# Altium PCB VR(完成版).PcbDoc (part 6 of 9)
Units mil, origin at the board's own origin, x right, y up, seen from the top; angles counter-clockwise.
Board outline 2839.68 x 2020.7 mil, 6 copper layers (TOP, GND02, SIN03, SIN04, PWR05, BOTTOM); 494 components, 404 nets, 7124 pads, 1123 vias.
Unrouted connection lines stored in the file: 10.
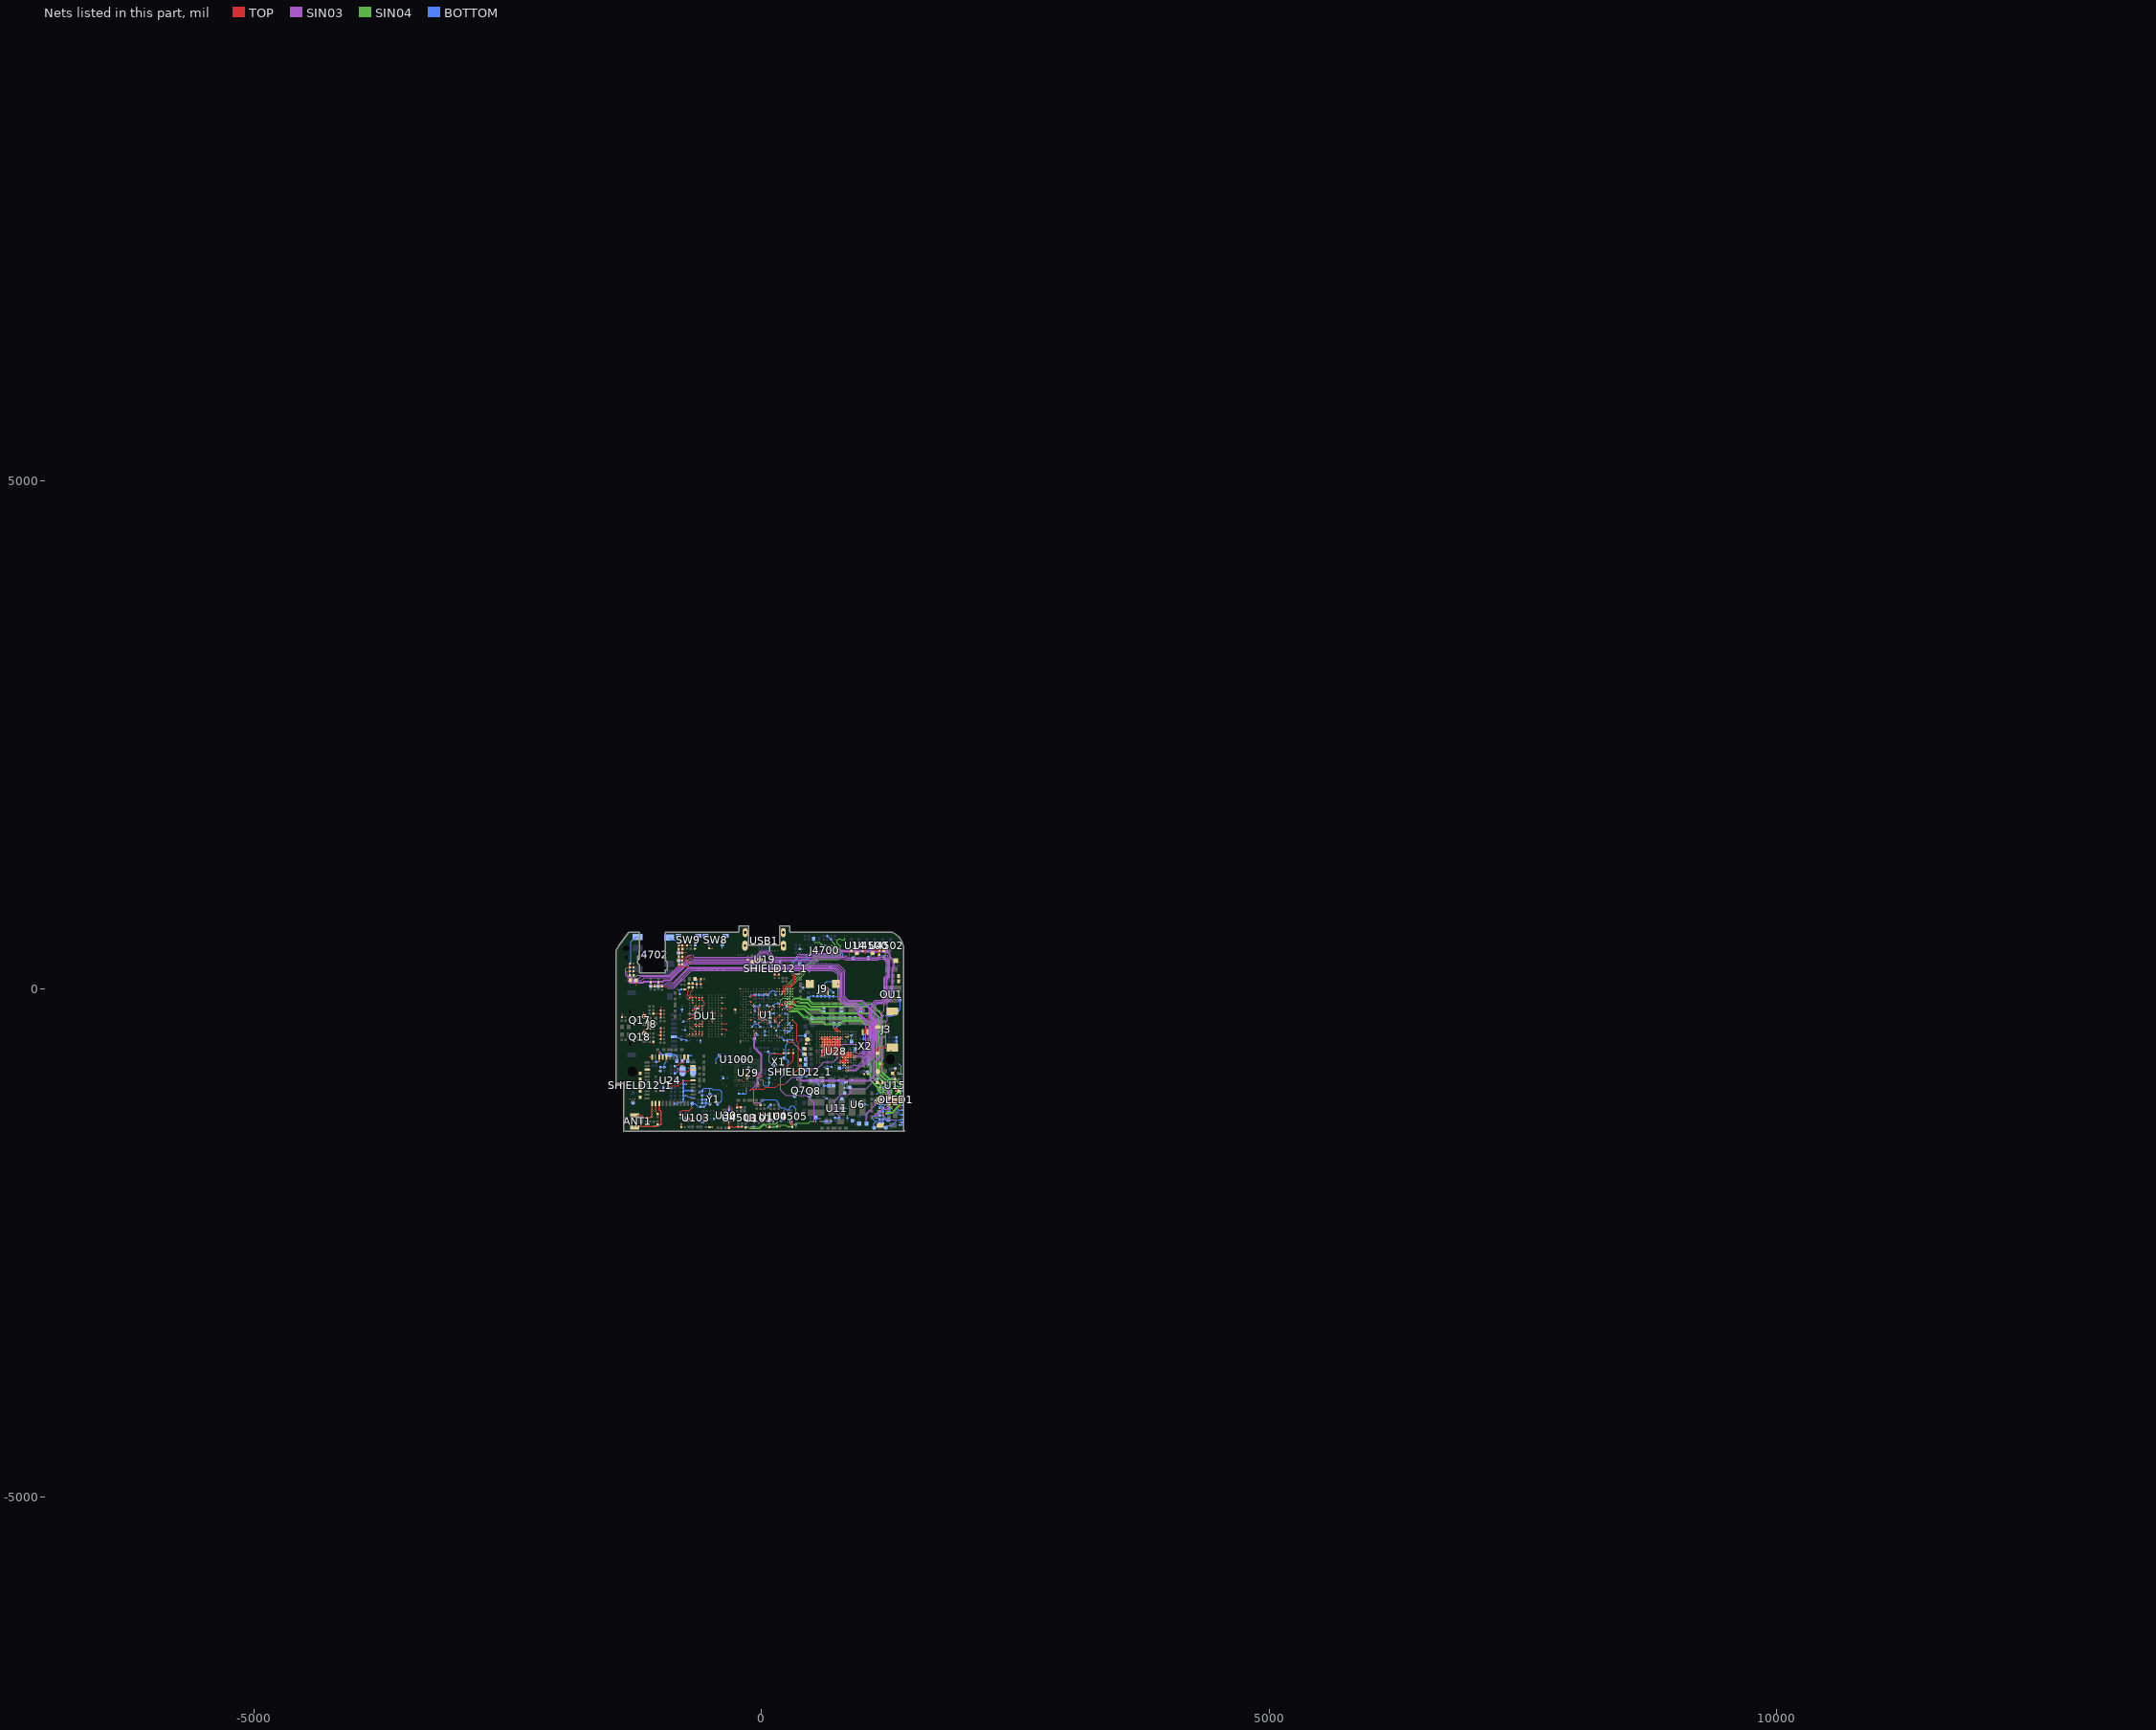
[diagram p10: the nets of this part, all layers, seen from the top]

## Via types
v1: diameter 14, hole 8, TOP to BOTTOM, tented both sides, 707 vias
v2: diameter 16, hole 10, TOP to BOTTOM, tented both sides, 275 vias
v3: diameter 16, hole 8, TOP to BOTTOM, tented both sides, 134 vias
v4: diameter 8, hole 8, TOP to BOTTOM, tented both sides, 3 vias
v5: diameter 10, hole 10, TOP to BOTTOM, tented both sides, 2 vias
v6: diameter 14, hole 8, TOP to BOTTOM, tented top, 1 vias
v7: diameter 14, hole 10, TOP to BOTTOM, tented both sides, 1 vias

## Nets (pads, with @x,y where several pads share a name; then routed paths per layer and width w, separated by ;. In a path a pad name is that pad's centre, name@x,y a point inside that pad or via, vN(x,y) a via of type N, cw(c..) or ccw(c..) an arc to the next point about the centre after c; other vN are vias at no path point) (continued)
GND: ANT1.2 ANT1.3 C3.2 C4.2 C5.1 C6.1 C7.2 C8.2 C11.1 C12.1 C13.2 C14.1 C15.2 C16.1 C17.1 C18.1 C19.1 C20.1 C21.1 C22.1 C23.1 C24.1 C25.1 C26.1 C27.1 C28.1 C29.1 C30.1 C31.1 C33.1 C34.1 C35.1 C36.1 C37.1 C38.1 C39.1 C41.1 C42.1 C43.1 C44.1 C45.1 C46.1 C47.1 C48.2 C50.2 C53.1 C56.2 C57.2 C59.2 C61.2 C63.2 C64.2 C65.1 C66.2 C67.2 C68.2 C69.1 C70.1 C71.1 C72.2 C74.1 C75.2 C76.1 C77.2 C78.1 C79.1 C81.1 C82.2 C83.2 C88.1 C89.1 C90.1 C91.1 C92.1 C93.1 C94.1 C95.1 C96.1 C98.1 C99.1 C100.1 C101.1 C117.1 C119.1 C130.1 C131.1 C132.1 C133.1 C134.1 C135.1 C136.1 C176.1 C179.1 C180.1 C182.1 C183.1 C184.1 C185.1 C186.1 C187.1 C188.1 C189.1 C190.1 C191.1 C197.2 C199.2 C200.1 C201.1 C202.2 C203.1 C204.2 C205.2 C216.2 C217.2 C218.2 C222.2 C226.1 C227.1 C228.1 C229.1 C230.1 C232.1 C233.1 C234.1 C236.2 C238.1 C239.2 C240.2 C241.2 C242.2 C247.2 C249.2 C261.2 C263.1 C265.1 C266.1 C267.1 C268.1 C269.1 C270.1 C271.2 C272.2 C273.2 C275.2 C276.1 C277.2 C278.2 C279.2 C280.1 C281.2 C282.2 C289.2 C290.1 C291.1 C292.2 C312.1 C313.1 C314.1 C315.1 C316.1 C317.1 C326.1 C327.1 C329.2 C331.2 C332.2 C333.2 C341.2 C4500.2 C4504.2 C4505.2 C4506.2 C4509.2 C4510.1 C4700.1 C4701.1 C4702.2 C4703.2 C4704.1 C4705.1 C4717.2 C4718.1 C4719.1 D2.2 D3.2 D13.2 D14.2 D15.2 D16.2 D17.2 D18.2 D19.2 D20.2 D21.2 D26.2 D27.2 D28.2 D29.2 D30.2 D31.2 D36.2 D37.2 D38.2 DC1.1 DC2.1 DC3.1 DC4.1 DC5.1 DC6.1 DC7.1 DC9.1 DC10.1 DC11.1 DC12.1 DC13.1 DC14.1 DC15.1 DC16.1 DC17.1 DC20.1 DC21.1 DC22.1 DC23.1 DR2.1 DR4.1 DR5.2 DR7.1 DU1.B2 DU1.B5 DU1.B6 DU1.B12 DU1.C3 DU1.C5 DU1.C6 DU1.D3 DU1.D12 DU1.E4 DU1.E5 DU1.E6 DU1.F4 DU1.F5 DU1.F6 DU1.F12 DU1.G3 DU1.G4 DU1.G6 DU1.G9 DU1.H2 DU1.H10 DU1.J4 DU1.J12 DU1.K2 DU1.K10 DU1.L6 DU1.L9 DU1.M4 DU1.M5 DU1.M6 DU1.M12 DU1.N4 DU1.N5 DU1.N6 DU1.P3 DU1.P12 DU1.R4 DU1.R5 DU1.R6 DU1.T2 DU1.T3 DU1.T4 DU1.T5 DU1.T6 DU1.T12 ED1.2 ED2.2 ED25.2 ED26.2 ED27.2 ED28.2 ED29.2 ED30.2 ED32.2 ED33.2 ED34.2 J3.3 J3.5 J3.6 J8.6 J8.10 J9.7 J9.8 J4700.1 J4700.3 J4700.16 J4700.25 J4700.29 J4700.31 OLED1.1 OLED1.7 OLED1.11 OLED1.15 OLED1.19 OLED1.23 OLED1.27 OLED1.31 OLED1.36 OLED1.40 OLED1.41 OU1.2 Q7.2 Q8.2 Q17.2 Q18.2 R8.2 R9.2 R14.2 R19.2 R23.2 R75.2 R87.2 R91.1 R137.1 R139.1 R149.1 R150.1 R151.1 R152.1 R168.1 R187.1 R193.1 R194.1 R325.1 R326.1 R465.1 R466.1 R478.1 R480.2 R484.1 R491.2 R1003.2 R1008.2 R1009.2 R4500.2 R4708.1 R5119.2 SHIELD12_1.1@141,198.14 SHIELD12_1.1@-1191.27,-949 SHIELD12_1.2@-1191.27,-1008.06 SHIELD12_1.3@383.73,-700.89 SHIELD12_1.3@-1191.27,-1067.11 SHIELD12_1.4@-1191.27,-889.94 SHIELD12_1.5@-1191.27,-830.89 SW8.2 SW8.3 SW8.4 SW9.2 SW9.3 SW9.4 TP62.1 TP71.1 U1.A1 U1.A21 U1.AA1 U1.AA21 U1.C7 U1.C11 U1.F5 U1.G6 U1.G16 U1.G17 U1.H6 U1.H8 U1.H12 U1.H14 U1.H16 U1.J8 U1.J13 U1.J17 U1.K5 U1.K8 U1.K9 U1.K10 U1.K11 U1.K12 U1.L8 U1.L16 U1.M8 U1.N5 U1.N9 U1.N10 U1.N11 U1.N12 U1.N14 U1.N17 U1.P8 U1.P12 U1.P16 U1.T14 U1.T18 U1.U6 U6.2 U11.2 U14.2 U15.2 U19.2 U24.1 U24.3 U24.20 U24.31 U24.33 U24.36 U28.D4 U28.D5 U28.D6 U28.D7 U28.E4 U28.E5 U28.E7 U28.F3 U28.F4 U28.F5 U28.F6 U28.G3 U28.G4 U28.G5 U28.G6 U28.G7 U28.G8 U28.G9 U28.G10 U28.G11 U28.G12 U28.G13 U28.G14 U28.H3 U28.H4 U28.H5 U28.H6 U28.H7 U28.H8 U28.H9 U28.H10 U28.H11 U28.H12 U28.H13 U28.H14 U28.J7 U28.J8 U28.J9 U28.J10 U28.J11 U28.J12 U28.J13 U28.J14 U28.K7 U28.K8 U28.K9 U28.K10 U28.K11 U28.K12 U28.K13 U28.K14 U28.L7 U28.L8 U28.L9 U28.L10 U28.L11 U28.L12 U28.L13 U28.L14 U28.M7 U28.M8 U28.M9 U28.M10 U28.M11 U28.M12 U28.M13 U28.M14 U28.N7 U28.N8 U28.N9 U28.N10 U28.N11 U28.N12 U28.N13 U28.N14 U28.P4 U28.P5 U28.P7 U28.P8 U28.P9 U28.P10 U28.P11 U28.P12 U28.P13 U28.P14 U29.AA4 U29.AA6 U29.K4 U29.M7 U29.P5 U29.R10 U29.U8 U29.Y2 U29.Y5 U30.11 U30.18 U30.20 U100.4 U100.8 U100.9 U101.3 U101.8 U101.11 U103.7 U1000.2 U4500.2 U4502.2 U4503.B1 U4505.1 U4505.6 U4505.7 USB1.5 USB1.6 USB1.7 USB1.8 USB1.9 X1.2 X1.4 X2.3 X2.4 Y1.2 Y1.4 | length 40403.1
  TOP w3.8: DU1.H2@-706.86,-241.03 -693.66,-254.23 v1@-656.29,-254.23
  TOP w4: DU1.K2@-706.49,-292.61 -696.17,-292.61 -683.08,-279.53 -666.4,-279.53 ; -662.99,-276.11 -651.08,-264.21 ; v1@-471.92,-303.66 -460.88,-292.61 DU1.K10@-454.52,-292.61 ; v1(-406.01,-253.02) -392.01,-267.02 DU1.J12@-391.53,-267.02 ; DU1.P12@-391.53,-394.98 -363.13,-394.98 -350.48,-407.63 -341.61,-407.63 v1(-331.01,-397.02) ; DU1.F12@-391.53,-190.25 v1@-347.23,-190.25
  TOP w5: -666.4,-279.53 -662.99,-276.11 ; -87.87,-64 -63.99,-64
  TOP w6: U24.36@-1126.27,-794.39 v1(-1086.61,-794.39) ; v1(-1102.67,-673.33) U24.33@-1076.08,-673.33 ; C201.1@-812.1,242.14 -812.1,222.1 -808,218 -732,218 v1(-721,229) ; U29.K4@-219.98,-898 v1(-182,-898) ; C13.2@132.86,140.28 C29.1@173,140.28 ; C13.2@133.73,142.87 v6(133.73,233.14)
  TOP w8: DU1.M12@-391.53,-343.8 v1@-348.81,-343.8 ; v1@-347.23,-190.25 v1(-346.26,-189.27)
  TOP w10: C326.1@-1371.1,-277.86 v1(-1371.1,-246.03) ; v1(-1322.94,210.81) D28.2@-1292.72,210.81 D27.2@-1292.72,249.14 ; v1(-1234.15,40.85) C190.1@-1234.15,85.14 ; Q18.2@-1152.27,-436.86 v1(-1152.27,-408.86) v1(-1134.27,-390.86) D14.2@-1095.37,-390.86 v1(-1095.37,-370.86) -1095.37,-341.86 C176.1@-1094.39,-341.86 ; Q17.2@-1152.27,-270.86 v1(-1152.27,-235.86) ; v1(-1064.92,-553.86) R480.2@-1064.92,-521.86 ; R478.1@-1064.92,-244.86 -992.62,-244.86 D20.2@-990.1,-247.37 ; R150.1@-1051.61,27.52 v1(-1051.61,51.48) ; v1(-1018.27,-456.86) D16.2@-990.1,-456.86 ; v2(-1005.22,-712.78) U24.31@-1005.22,-673.33 -1005.22,-627.22 v1(-1004,-626) ; D21.2@-990.1,-494.01 D16.2@-990.1,-458.78 D16.2@-990.1,-456.86 ; D18.2@-990.1,-388.31 D17.2@-990.1,-423.54 D16.2@-990.1,-456.86 ; D19.2@-990.1,-282.61 D20.2@-990.1,-247.37 ; v1(-990.1,-183.03) D15.2@-990.1,-212.14 D20.2@-990.1,-247.37 ; R151.1@-978.27,27.52 -953.48,27.52 -941,40 v1(-941,66) ; v1(-825,-786) -800,-811 -720,-811 -703.39,-794.39 U24.20@-671.55,-794.39 ; C333.2@-796.2,-1240.1 -796.2,-1213.2 -778,-1195 -707,-1195 -681.15,-1169.15 v2(-681.15,-1159) ; DC9.1@-756.72,-4.86 v1(-732.14,-4.86) ; v1(-744.06,354.94) C200.1@-779.82,354.94 D26.2@-779.82,430.14 -731.44,430.14 C79.1@-730.27,428.97 ; v1(-724.82,-297.23) -724.61,-297.02 -710.9,-297.02 DU1.K2@-706.49,-292.61 ; v1(-724.58,-241.43) DU1.H2@-706.49,-241.43 ; v1(-720.13,-100.68) DU1.B2@-707.33,-87.89 ; v1@-719.28,-458.95 DU1.T2@-706.49,-446.16 ; DR2.1@-715.27,53.35 -710.34,48.43 DC10.1@-637.27,48.43 DC23.1@-596.27,48.43 ; v1(-693.69,-382.18) -680.9,-394.98 DU1.P3@-674.99,-394.98 ; v1(-688.63,-433.36) DU1.T3@-675.84,-446.15 ; v1(-688.63,-100.68) -675.84,-113.48 -679.42,-117.06 -679.42,-135.48 DU1.D3@-675.84,-139.07 ; v1@-687.78,-458.95 DU1.T3@-674.99,-446.16 ; v1@-659.74,-353.46 v1@-659.42,-353.46 ; v1(-657.13,-407.77) -644.34,-420.56 -644.34,-445.31 DU1.T4@-643.49,-446.16 v1@-656.29,-458.95 ; v1@-656.29,-254.23 DU1.J4@-643.49,-267.02 ; D2.2@-656.27,395.69 v1(-632.82,395.69) ; DC12.1@-652.15,98.14 v1(-623.14,98.14) ; DU1.F4@-643.49,-190.25 v1(-656.29,-177.46) DU1.E4@-643.49,-164.66 ; v1(-625.79,-77.09) -622.79,-77.09 DU1.B5@-612,-87.89 DU1.C5@-612,-113.48 ; v1@-624.79,-458.95 DU1.T5@-612,-446.16 DU1.R5@-612,-420.57 ; DU1.M5@-612,-343.8 -606.09,-343.8 v1(-593.3,-356.59) ; DU1.F5@-612,-190.25 v1(-624.79,-177.46) DU1.E5@-612,-164.66 ; v1@-596.27,72.27 DC23.1@-596.27,48.43 ; v1(-593.3,-203.05) DU1.G6@-580.5,-215.84 ; v1@-593.3,-458.95 DU1.T6@-580.5,-446.16 DU1.R6@-580.5,-420.57 ; v1@-593.3,-75.09 DU1.B6@-580.5,-87.89 -580.5,-88.31 -588.08,-95.89 -588.08,-105.9 DU1.C6@-580.5,-113.48 -580.5,-117.11 -558.86,-138.75 -558.86,-152.81 -568.58,-162.53 DU1.E6@-578.58,-162.53 ; DC11.1@-593.28,96 -596.27,93.01 DC23.1@-596.27,48.43 ; DU1.N6@-580.5,-369.39 v1(-593.3,-356.59) ; DU1.L6@-580.5,-318.2 DU1.M6@-580.5,-343.8 v1(-593.3,-356.59) ; DU1.F6@-580.5,-190.25 v1(-593.3,-177.46) DU1.E6@-580.5,-164.66 ; D38.2@-515.27,399.86 v1@-487.56,399.86 ; DU1.L9@-486.01,-318.2 v1(-473.22,-331) ; DU1.G9@-484.08,-216.14 -479.81,-216.14 DU1.H10@-454.52,-241.43 ; DU1.T12@-391.53,-446.16 v1@-378.58,-446.16 ; DU1.D12@-391.53,-139.07 v1@-373.43,-139.07 ; DU1.B12@-391.53,-87.89 -386.55,-82.91 -377.01,-82.91 v1@-375.74,-81.63 ; v1@-348.81,-343.8 -347.03,-342.02 v1(-344.01,-342.02) ; v2(-314.27,-1154.86) -286.21,-1182.92 U30.18@-286.21,-1209.49 ; v1(-221.98,0) U1.A1@-203.88,0 ; U29.K4@-221.22,-896.76 U29.K4@-219.98,-898 ; v1(-204.03,-530.91) U1.AA1@-204.03,-511.96 ; U29.M7@-181.85,-837.7 -145.7,-837.7 -135,-827 v1(-135,-807) -122.8,-794.8 U29.R10@-122.8,-778.65 ; U29.P5@-142.48,-877.07 -142.48,-891.52 v1(-135,-899) ; v1(-115.15,-294.29) U1.N5@-102.36,-307.09 ; v1(-115.15,-243.11) U1.K5@-102.36,-230.32 ; v1(-114.3,-115.17) U1.F5@-101.51,-127.96 ; v1(-113.46,-89.58) -87.87,-64 ; C184.1@-85.27,266.02 -63.15,288.14 U19.2@-16.45,288.14 ; U29.U8@-83.43,-818.02 v1(-64.02,-818.02) ; U1.U6@-76.77,-409.45 v1(-63.97,-422.24) ; U1.H6@-75.92,-179.14 v1(-88.72,-166.34) U1.G6@-75.92,-153.56 ; -63.99,-64 U1.C7@-51.18,-51.19 U1.C7@-51.18,-52.04 ; v1(-38.39,-345.48) U1.P8@-25.59,-332.68 ; v1(-38.39,-294.3) U1.M8@-25.59,-281.5 U1.N9@0,-307.09 v1(12.79,-319.89) U1.N10@25.59,-307.09 ; v1(-38.39,-268.7) U1.L8@-25.59,-255.91 -12.79,-243.11 ; v1(-38.39,-191.93) U1.H8@-25.59,-179.14 ; v1(-38.39,-191.93) U1.J8@-25.59,-204.73 ; v1(-24.37,-971.63) U29.Y2@-24.37,-936.13 ; U29.Y5@-24.37,-877.07 U29.AA6@-4.69,-857.39 v1(20.39,-857.39) ; U29.AA4@-4.69,-896.76 v1(20.76,-896.76) ; U1.K9@0,-230.32 v1(-12.8,-217.52) U1.J8@-25.59,-204.73 ; v1(38.39,-38.39) U1.C11@51.18,-51.19 ; U1.N11@51.18,-307.09 v1(63.98,-319.89) ; v1@63.98,-345.48 U1.P12@76.77,-332.68 v1(63.98,-319.89) ; U1.N12@76.77,-307.09 v1(63.98,-319.89) ; U1.H12@76.77,-179.14 v1(89.57,-166.34) ; v1(94,-640) 212.92,-640 C8.2@222,-630.92 C8.2@223.36,-632.28 ; U1.N14@127.95,-307.09 v1(166.33,-345.48) U1.P16@179.13,-332.68 U1.N17@204.72,-307.09 v1(217.52,-294.29) ; U1.T14@127.95,-383.86 v1(140.75,-396.65) ; U1.N14@127.95,-307.09 U1.L16@179.13,-255.91 v1(191.93,-268.7) ; U1.H14@127.95,-179.14 U1.K12@76.77,-230.32 v1(63.98,-217.52) U1.K11@51.18,-230.32 38.39,-217.52 U1.K10@25.59,-230.32 v1(12.79,-217.52) -12.79,-243.11 ; v1(172.86,-793) 225,-793 314,-704 C280.1@314,-632.28 313,-631.28 C277.2@268,-631.28 ; U1.H16@179.13,-179.14 U1.G17@204.72,-153.55 v1(191.92,-140.76) U1.G16@179.13,-153.55 ; U1.J17@204.72,-204.73 v1(217.52,-191.93) ; U1.T18@230.31,-383.86 v1(243.11,-396.65) ; U1.AA21@307.09,-511.82 v1(319.89,-499.01) ; U1.A21@307.09,0 v1(319.89,12.8) ; R14.2@438.06,-540.48 438.06,-513.8 C265.1@454,-497.86 ; 661.84,-638.62 U28.G11@674.63,-651.42 ; U28.H11@674.63,-625.83 v3(687.44,-638.63) ; U28.P5@828.18,-472.28 U28.P4@853.77,-472.28 ; v1@866.73,321.14 866.73,354.86 C204.2@886.73,374.86 ; v1(923.73,325.14) 923.73,334.02 C205.2@940.73,351.02 ; C4506.2@996.73,374.31 1013.69,374.31 1023.73,364.27 v1@1023.73,339.14 ; v1(1078.23,325.14) 1078.23,332.52 C4504.2@1096.73,351.02 1125.02,379.31 C4509.2@1161.73,379.31 ; C117.1@1143.73,-635.86 C117.1@1143.73,-635.33 ; 1143.73,-601.86 C117.1@1143.73,-635.33 ; C132.1@1146.38,-812.61 1173.73,-785.26 C119.1@1173.73,-737.86 1205.73,-737.86 v2@1205.73,-736.86 ; R4500.2@1161.73,337.52 C4509.2@1161.73,379.31 ; J3.3@1176.25,-374.25 1219.33,-374.25 v2(1247.73,-345.86) ; C4510.1@1204.61,378.14 1203.44,379.31 C4509.2@1162.73,379.31 C4509.2@1161.73,379.31 ; v2(1226.73,-1159.86) 1231.73,-1159.86 1258.56,-1133.02 C16.1@1258.56,-1129.83 ; J3.5@1290.42,-576.02 1157.98,-576.02 1143.73,-590.27 C117.1@1143.73,-635.33 ; U15.2@1316.73,-898.86 1316.73,-856.98 C216.2@1292.61,-832.86 1321.87,-803.6 C133.1@1321.87,-782.86 ; D3.2@1321.13,276.14 1325.13,272.14 v1(1362.73,272.14) ; v2(1354.16,-1179) 1379,-1154.16 C236.2@1379,-1105.28 ; v1@-659.42,-353.46 -659.08,-353.8 DU1.N4@-643.49,-369.39 -637.59,-369.39 -624.79,-356.59 ; v1@-659.42,-353.46 -655.44,-353.46 -645.78,-343.8 DU1.M4@-643.49,-343.8 -643.49,-346.59 -633.49,-356.59 -624.79,-356.59 ; -624.79,-356.59 DU1.N5@-612,-369.39 -606.09,-369.39 v1(-593.3,-356.59) ; U1.AA1@-204.03,-511.96 -203.88,-511.82 U1.AA1@-204.03,-511.96 ; U1.J8@-25.59,-204.73 v1(-38.39,-217.52) U1.K8@-25.59,-230.32 -12.79,-243.11
  TOP w11.81: ANT1.2@-1247.29,-1246.79 -1179.34,-1246.79 v2(-1161.27,-1264.86) -1082.27,-1264.86 v2(-1076.08,-1258.67) U24.1@-1076.08,-1128.05 ; v2(-1196.27,-1352.86) -1030.86,-1352.86 -1020,-1342 -995.41,-1342 v2(-987.27,-1333.86) -987.27,-1208.86 -1005.22,-1190.91 U24.3@-1005.22,-1128.05 ; C331.2@-787.1,-1360.86 v2(-787.1,-1332.03) ; U103.7@-732.85,-1283.65 v2(-676.27,-1283.65) ; C329.2@-512.44,-1360.86 -511.44,-1361.86 v2(-485.27,-1361.86) ; U30.11@-321.65,-1307.92 -321.65,-1323.48 -316.89,-1328.24 R168.1@-316.89,-1366.86 -308.72,-1358.69 C191.1@-228.27,-1358.69 C189.1@-192.27,-1358.69 ; U30.20@-321.65,-1189.8 -321.65,-1162.24 v2(-314.27,-1154.86) ; v2(-250.07,-1269.06) U4503.B1@-228.97,-1269.06 ; v1(-239.27,-1135.86) C186.1@-239.27,-1168.03 -237.72,-1166.48 R491.2@-202.55,-1166.48 ; v7(-100.27,-1304) -100.27,-1284.27 -88.86,-1272.86 U101.3@-74.58,-1272.86 ; U101.8@20.03,-1292.54 51.41,-1292.54 v2(55.73,-1296.86) 76.55,-1296.86 U100.4@90.02,-1283.39 ; U101.11@20.03,-1233.49 20.03,-1220.55 v2(27.23,-1213.36) ; U100.8@151.44,-1263.7 U100.9@151.44,-1244.02 170.57,-1244.02 190.26,-1224.33 U4505.1@221.69,-1224.33 v2(221.69,-1195.9) ; C179.1@154.73,-1356.69 v2(183.56,-1356.69) ; U4505.6@281.73,-1304.05 281.73,-1326.86 287.73,-1332.86 v2@301.41,-1332.86 ; U4505.7@301.41,-1304.05 v2@301.41,-1332.86 ; C4719.1@303.56,-1359.86 301.41,-1357.71 v2(301.41,-1333.86) v2@301.41,-1332.86 ; v3(585.07,-664.22) U28.G14@597.86,-651.42 ; v3(585.07,-638.63) U28.H14@597.86,-625.83 U28.K12@649.04,-574.65 v3(661.84,-561.85) ; v3(585.07,-561.85) U28.K14@597.86,-574.65 v3(610.66,-561.85) ; U28.J14@597.86,-600.24 U28.G12@649.04,-651.42 U28.J10@700.23,-600.24 U28.K9@725.82,-574.65 ; U28.L14@597.86,-549.05 v3(610.66,-536.26) ; v3(610.66,-664.22) U28.G13@623.45,-651.42 U28.K10@700.23,-574.65 ; v3(610.66,-638.63) U28.H13@623.45,-625.83 U28.J12@649.04,-600.24 v3(661.84,-587.44) ; v3(610.66,-587.44) U28.J13@623.45,-600.24 661.84,-638.62 U28.G11@674.63,-651.42 ; U28.M13@623.45,-523.46 636.25,-536.26 ; U28.P13@623.45,-472.28 610.66,-485.08 ; U28.P12@649.04,-472.28 v3(636.25,-485.07) ; U28.H11@674.63,-625.83 U28.K13@623.45,-574.65 ; U28.P11@674.63,-472.28 v3(661.84,-485.07) ; U28.N10@700.23,-497.87 U28.M9@725.82,-523.46 U28.L8@751.41,-549.05 ; U28.P10@700.23,-472.28 738.62,-510.66 ; U28.P9@725.82,-472.28 U28.L12@649.04,-549.05 U28.K13@623.45,-574.65 ; v3(764.21,-587.44) U28.J8@751.41,-600.24 U28.G10@700.23,-651.42 v3(687.44,-638.63) U28.H10@700.23,-625.83 U28.L7@777,-549.05 U28.M8@751.41,-523.46 ; 764.21,-536.26 U28.M7@777,-523.46 764.21,-510.67 ; U28.D7@777,-728.19 U28.H3@879.36,-625.83 v3(892.16,-638.63) U28.D6@802.59,-728.19 ; U28.E7@777,-702.6 U28.D6@802.59,-728.19 ; U28.G7@777,-651.42 U28.H6@802.59,-625.83 ; U28.J7@777,-600.24 U28.L9@725.82,-549.05 v3(713.03,-536.26) ; U28.P7@777,-472.28 v3(789.8,-485.07) U28.N7@777,-497.87 764.21,-510.67 ; 789.38,-613.45 U28.H7@777,-625.83 ; 789.79,-663.21 827.17,-625.83 U28.H5@828.18,-625.83 840.98,-638.62 U28.G4@853.77,-651.42 U28.F3@879.36,-677.01 892.16,-664.22 U28.G3@879.36,-651.42 866.57,-638.62 U28.H4@853.77,-625.83 ; v3(815.39,-740.98) U28.D6@802.59,-728.19 ; v3(815.39,-740.98) U28.D5@828.18,-728.19 ; U28.E5@828.18,-702.6 U28.D4@853.77,-728.19 ; 840.98,-715.4 U28.E4@853.77,-702.6 ; U28.H4@853.77,-625.83 U28.F6@802.59,-677.01 U28.K10@700.23,-574.65 ; U28.P4@853.77,-472.28 v3(866.56,-459.49) ; X2.3@1001.19,-426.06 1024,-426.06 ; C233.1@1012.66,-838.69 C232.1@1052.66,-838.69 ; v2(1044,-378.57) 1024,-398.57 1024,-426.06 ; X2.4@1048.44,-426.06 1024,-426.06 ; U28.N14@597.86,-497.87 610.66,-485.08 ; U28.N14@597.86,-497.87 v3(661.84,-561.85) ; U28.N14@597.86,-497.87 v3(585.07,-485.07) U28.P14@597.86,-472.28 610.66,-485.07 ; v3(610.66,-561.85) 661.84,-510.66 ; v3(610.66,-561.85) U28.K13@623.45,-574.65 ; v3(610.66,-536.26) v3(661.84,-485.07) ; v3(610.66,-536.26) U28.L13@623.45,-549.05 v3(661.84,-587.44) ; v3(610.66,-536.26) U28.M14@597.86,-523.46 v3(636.25,-485.07) ; 610.66,-485.07 U28.N13@623.45,-497.87 U28.M12@649.04,-523.46 U28.L11@674.63,-549.05 U28.K10@700.23,-574.65 ; v3(636.25,-485.07) 661.84,-510.66 ; v3(661.84,-587.44) U28.K11@674.63,-574.65 ; v3(661.84,-587.44) U28.J11@674.63,-600.24 U28.G9@725.82,-651.42 U28.J7@777,-600.24 ; v3(661.84,-561.85) U28.M10@700.23,-523.46 v3(713.03,-510.66) U28.P8@751.41,-472.28 v3(764.21,-485.07) U28.N8@751.41,-497.87 738.62,-510.67 ; v3(661.84,-561.85) U28.K11@674.63,-574.65 ; 661.84,-510.67 U28.N11@674.63,-497.87 ; 661.84,-510.66 U28.M11@674.63,-523.46 v3(713.03,-561.85) ; v3(661.84,-485.07) U28.N11@674.63,-497.87 ; U28.K11@674.63,-574.65 U28.G8@751.41,-651.42 v3(764.21,-638.63) U28.H7@777,-625.83 ; U28.K11@674.63,-574.65 U28.L10@700.23,-549.05 v3(713.03,-536.26) ; U28.N11@674.63,-497.87 v3(713.03,-536.26) ; U28.K10@700.23,-574.65 v3(713.03,-561.85) ; v3(713.03,-561.85) U28.M8@751.41,-523.46 ; v3(713.03,-561.85) U28.K9@725.82,-574.65 ; v3(713.03,-536.26) 738.62,-510.66 ; U28.K9@725.82,-574.65 U28.H7@777,-625.83 ; U28.K9@725.82,-574.65 U28.L8@751.41,-549.05 ; 738.62,-510.66 U28.M8@751.41,-523.46 ; U28.L8@751.41,-549.05 v3(789.8,-587.44) U28.J7@777,-600.24 ; U28.M8@751.41,-523.46 764.21,-510.67 ; U28.H7@777,-625.83 U28.F5@828.18,-677.01 v3(840.98,-689.81) U28.F4@853.77,-677.01 v3(840.98,-664.22) U28.G5@828.18,-651.42 U28.J7@777,-600.24
  TOP w12: DU1.G3@-675.84,-215.84 -666.9,-206.9 -653.28,-206.9 -644.34,-215.84 DU1.F4@-644.34,-190.25 ; v1(-274.01,-202.02) -271.29,-204.74 DC7.1@-254.01,-204.74
  SIN03 w6: -1339,194.75 -1339,132 -1276,69 -1166,69 -1159,76 -972,76 -956,92 -894,92 -714,272 -697,272 ; -1295,198 -1295,129 -1260,94 -1215,94 -1186,123 -899,123 -739,283 -739,305 -714,330 v1(-678,330) -661,313 -65,313 -4,374 71,374 132,313 516,313 544,341 767,341 792,366 1206.87,366 v1(1232.73,340.14) 1247,325.87 1247,309 1266,290 1266,122 1240,96 1240,-107 1201,-146 1145,-146 1127,-164 1127,-253 1153,-279 1153,-526 1138,-541 1138,-647 1039,-746 ; v1@-940,65 -868,65 -717,216 736,216 794,158 794,-85 842,-133 933,-133 1008,-208 1008,-233 1037,-262 v2(1037,-281) 1037,-284 1084,-331 1084,-487 1070,-501 1070,-601 1012.5,-658.5 ; v1(-921,8) -861,8 -687,182 710,182 754,138 754,-102 824,-172 902,-172 951,-221 951,-259 1029,-337 1029,-581 987,-623 966,-623 ; -697,278.44 -697,272 ; v1(-697,286) -697,272 ; 996,-731 1103,-624 1103,-524 1118,-509 1118,-313 1086,-281 1086,-147.02 1121.02,-112 1183,-112 1206,-89 1206,110.08 1232,136.08 1232,264.92 1200.92,296 1161,296 1152,287 831,287 817,301 581,301 552,272 -697,272
  SIN03 w10: -1339,194.75 v1(-1322.94,210.81)
  SIN04 w6: v1(191.92,-140.76) 191.92,-113.08 215.02,-89.98 268.02,-89.98 288,-70 288,18 559,289 761,289 778,306 778,415 745,448 745,480 758,493 780,493 792,481 817,481 821,485 v1(821,510) ; 196,-66 196,-54 241,-9 241,26 541,326 706.32,326 v1(729.92,349.6) 730,349.68 730,394 696,428 604,428 570.86,461.14 v1(523.73,461.14) ; v1(243.1,-63.98) 266,-41.09 266,23 550,307 731,307 754,330 754,404.53 v1(687.06,471.47)
  BOTTOM w5: v1(-63.97,-422.24) -63.97,-426.31 C3.2@-40.14,-450.14
  BOTTOM w6: v1(-1013.24,-807.24) R466.1@-993.27,-807.24 ; v1(-821,-5) DC4.1@-788.28,-5 -802.27,-18.99 DC21.1@-802.27,-53.57 ; D29.2@-779.82,239.14 -731.14,239.14 v1(-721,229) ; v6@133.73,237.14 158.87,212 165,212 184.73,231.73 C182.1@184.73,270.41 ; C4702.2@378.61,245.14 378.61,272.61 401.14,295.14 445.73,295.14 ; v1(468,356.14) 468,324.55 J4700.3@470.07,322.48
  BOTTOM w8: R1009.2@1163.35,-1168.24 C4717.2@1196.73,-1134.86
  BOTTOM w10: R194.1@-1034.89,-718.86 -1028.82,-712.78 v2(-1005.22,-712.78) ; R193.1@-965,-974.31 v1(-965,-949) ; J8.6@-859.74,-472.81 v1(-818.23,-472.81) -791.89,-499.14 DC17.1@-785.27,-499.14 -747.86,-499.14 DC1.1@-736.58,-510.42 ; C238.1@-854.82,-1130.86 -824.86,-1130.86 -809,-1115 -775,-1115 -767.44,-1107.44 C312.1@-767.44,-1089.86 ; R465.1@-853.27,-832.48 -845.48,-832.48 -825,-812 v1(-825,-786) ; v1(-785.41,-339) DC15.1@-766.27,-319.86 ; v1@-780.42,-233.9 DC20.1@-780.42,-204.19 ; v1(-779.86,-405.14) DC3.1@-751.27,-405.14 ; v2(-736.27,-1051.11) -726.52,-1060.86 -701.27,-1060.86 -695.27,-1066.86 -658.14,-1066.86 ; v1(-724.58,-241.43) -718.1,-247.91 -662.61,-247.91 v1@-656.29,-254.23 ; v2(-681.15,-1159) C234.1@-681.15,-1129.86 -652.14,-1129.86 -615.97,-1166.03 C241.2@-597.1,-1166.03 ; v1(-656.29,-177.46) -656.29,-200.75 -652.14,-204.9 ; DC6.1@-637,48.14 -637,84.28 v1(-623.14,98.14) ; -618.13,-1026.13 -598,-1006 C240.2@-583.28,-1006 -583.28,-997.28 -564,-978 -523,-978 ; v1(-598.91,-536.91) DC22.1@-598.91,-510.42 ; v1(-476.83,-1037.17) Y1.4@-505.99,-1037.17 -505.99,-995.01 -523,-978 ; v1@-447,-1099.86 -428.03,-1118.83 -408.01,-1118.83 -388,-1098.82 -388,-1016.01 -412,-992.01 -479.99,-992.01 -494,-978 -523,-978 ; v1(-447,-732) -447,-692 C341.2@-413,-658 ; v1(-383.92,400.79) SW8.2@-383.92,446.37 ; R326.1@-375.38,-878 v1(-375.38,-849.38) ; v1@-234,-674 -213,-695 U1000.2@-181.16,-695 ; C96.1@-220.6,-1032.69 C95.1@-181.64,-1032.69 -155.69,-1032.69 -145,-1022 v1(-145,-973) ; v1(-135,-899) -135,-874.28 C101.1@-128.72,-868 ; -129,-798 -129,-776.17 C99.1@-125.83,-773 ; v1@-129,237.14 R137.1@-42.65,237.14 -38.27,241.52 D36.2@-38.27,275.31 D31.2@-1.27,275.31 D30.2@34.73,275.31 ; v1(-113.46,-89.58) -113.46,-71.46 -100.72,-58.72 C20.1@-64,-58.72 -63,-59.72 C12.1@-22,-59.72 C46.1@18,-59.72 19,-58.72 36,-58.72 ; C22.1@-92.28,-373 -92.28,-372.28 -65.9,-345.9 v1@-41.99,-345.9 ; v1(-88.72,-166.34) DC5.1@-66.58,-166.34 ; DC13.1@-66.08,-329.81 DC13.1@-62.08,-325.81 ; DR5.2@-63.98,-490.31 -63.98,-473.98 C3.2@-40.14,-450.14 ; DC14.1@-62.08,-215.96 DC5.1@-62.08,-170.67 ; DC13.1@-57.21,-325.81 DC13.1@-62.08,-325.81 ; DC5.1@-56.22,-170.67 DC5.1@-62.08,-170.67 ; v1(-38.39,-345.48) v1@-38.39,-345.9 ; v1(-38.39,-294.3) -36.95,-292.86 C25.1@-12,-292.86 ; R325.1@-36.31,-924 -36.31,-959.69 v1(-24.37,-971.63) ; C39.1@-22.28,-243 -22.28,-227.01 v1(-12.8,-217.52) ; C47.1@-19.62,-166.34 C47.1@-15,-161.72 -32.72,-161.72 -41.67,-170.67 DC5.1@-62.08,-170.67 ; C24.1@-13.28,-371 v1@-38.39,-345.9 ; v1(12.79,-319.89) 36.96,-295.72 C26.1@39,-295.72 ; v1(20.76,-896.76) 20.39,-896.39 20.39,-945.39 29,-954 66,-954 76.28,-943.72 C98.1@76.28,-925 76.28,-877 C100.1@77.28,-876 ; C5.1@35.72,-458 C7.2@35.72,-418 38.39,-415.33 v1(38.39,-396.65) ; v1(38.39,-38.39) 38.39,-56.33 36,-58.72 ; C45.1@58.28,-163 61.62,-166.34 v1(89.57,-166.34) ; v1(63.98,-319.89) 85.6,-319.89 C41.1@89,-323.28 89,-344.91 89.57,-345.48 89.57,-362.28 C27.1@96.28,-369 ; v1(63.98,-217.52) 75.52,-217.52 80.28,-222.28 C38.1@80.28,-243 C38.1@81.28,-242 ; R8.2@68,-619.86 88.14,-640 v1(94,-640) 77,-657 77,-717.14 152.86,-793 v1(172.86,-793) 247,-793 260,-780 260,-724.5 268,-716.5 233.36,-681.86 242.81,-672.41 C28.1@242.81,-634.86 242.81,-553.19 254.14,-541.86 C42.1@254.14,-503 258.13,-499.01 v1(319.89,-499.01) ; C38.1@89.57,-233.72 C38.1@81.28,-242 ; v1@96.14,-634.86 C31.1@129.91,-634.86 ; R139.1@106.11,237.14 v6@133.73,237.14 ; R139.1@106.73,237.76 D37.2@106.73,275.31 ; C15.2@118,-164.86 140.14,-142.72 C33.1@163,-142.72 ; C19.1@121.72,-242 C38.1@81.28,-242 ; C21.1@138,-322.28 143.14,-322.28 v1(166.33,-345.48) 166.33,-365.05 C35.1@169.28,-368 ; C4.2@140,-61.72 140,-33 122,-15 106.72,-15 C44.1@63,-58.72 36,-58.72 ; C33.1@162.72,-143 C33.1@163,-142.72 ; v1(191.92,-140.76) 164.96,-140.76 C33.1@163,-142.72 ; v1@217.25,-294.03 v1(217.52,-294.29) ; v1(217.52,-191.93) 241.07,-191.93 246.28,-186.72 C36.1@246.28,-168 ; C11.1@224.28,-410 229.76,-410 v1(243.11,-396.65) ; C11.1@232.57,-418.28 280.72,-418.28 296,-403 296,-373 C18.1@268,-345 264,-341 264,-248 260,-244 C34.1@234.28,-244 ; v2(329.91,-1004.04) 433.1,-1004.04 Q8.2@478.91,-1049.86 ; 359.35,-459.24 C263.1@432.29,-459.24 ; R4708.1@376.11,393.98 v1(400.89,393.98) ; ED30.2@412.73,10.76 413.73,9.76 v1(413.73,-16.86) ; J4700.1@446.45,322.48 445.73,321.76 445.73,295.14 459.73,295.14 470.07,305.49 J4700.3@470.07,322.48 ; C282.2@463.73,-92.98 487.02,-69.69 C281.2@510.93,-69.69 512.48,-71.24 ED28.2@550.53,-71.24 ED29.2@590.13,-71.24 ED32.2@629.73,-71.24 ED33.2@669.33,-71.24 ; v1(473.61,166) 480.73,173.12 C4705.1@480.73,217.36 ; C4703.2@514.61,494.37 514.61,470.26 v1(523.73,461.14) ; v2(539.85,-1305.86) C267.1@539.85,-1268.98 539.85,-1276.86 v2(580.73,-1276.86) ; v2(581.73,-1305.24) R91.1@644.41,-1305.24 644.41,-1303.69 C136.1@685.21,-1303.69 ; v2(602.73,-1062.86) v2(627.58,-1062.86) C131.1@642.58,-1077.86 ; v3(613,-770) 639.55,-770 C77.2@648.41,-778.86 660.13,-767.14 C226.1@692.73,-767.14 ; v1(623.62,406.25) J4700.16@623.62,431.14 ; C4701.1@650.64,519.97 653.9,519.97 686.18,487.69 C4700.1@687.06,487.69 v1(687.06,471.47) ; v1(669.33,-102.26) ED33.2@669.33,-71.24 ; C4704.1@677.73,217.36 699.03,196.05 v1(699.03,172.97) ; v3(713.03,-587.44) 731.31,-587.44 738.73,-594.86 C75.2@738.73,-621.74 ; J4700.25@729.92,322.48 v1(729.92,349.6) ; 739.11,-71.24 ED34.2@708.93,-71.24 ED33.2@669.33,-71.24 ; C72.2@769.41,-780.98 799.02,-780.98 815.39,-764.61 v3(815.39,-740.98) ; J4700.29@777.16,322.48 v1(777.16,349.6) 793.27,349.6 800.78,342.09 J4700.31@800.78,322.48 ; U11.2@803.25,-1173.86 U11.2@803.25,-1174.86 v2(844.73,-1174.86) ; C227.1@840.98,-475.63 850.42,-475.63 v3(866.56,-459.49) ; C134.1@848.41,-1271.41 v2(848.41,-1235.86) ; C50.2@886.53,-518.24 886.53,-460.57 887.62,-459.49 C230.1@890.41,-456.69 ; v3(892.16,-638.63) 927.79,-603 C273.2@927.79,-594.86 ; v2(896.41,-1330.86) C135.1@896.41,-1297.98 ; C4500.2@907.61,304.14 923.73,320.26 U14.2@923.73,377.14 ; R9.2@962.41,-1326.6 v2(962.41,-1293.86) ; U6.2@998.59,-1138.86 v2@1050.73,-1138.86 ; C228.1@1008.01,-492.86 1008.01,-456.99 1044,-421 v2(1044,-378.57) ; C197.2@1008.24,-633.86 1008.24,-597.52 C229.1@1007.59,-596.86 1059.41,-596.86 TP62.1@1061.41,-598.86 1061.41,-681.71 C6.1@1058.12,-685 1058.12,-736.06 C202.2@1059.06,-737 1085,-762.94 1085,-811 1074,-822 C78.1@1042.06,-822 ; C199.2@1054.61,307.14 v1@1075.42,327.95 ; v1@1078.23,330.76 U4500.2@1078.23,377.14 ; v1(1119.73,-1035) 1142.52,-1035 C261.2@1166.9,-1010.63 1167.9,-1009.63 C222.2@1167.9,-973.63 ; v2(1121.73,-1292.86) 1107.73,-1292.86 1094.73,-1279.86 1094.73,-1262.86 1105.73,-1251.86 1158.35,-1251.86 R75.2@1163.35,-1246.86 ; v2(1137.73,-1325.86) 1160.35,-1325.86 R1008.2@1163.35,-1322.86 ; R87.2@1139.61,-836.63 1139.61,-750.39 1152,-738 v2(1209,-738) ; R1009.2@1163.35,-1170.86 R1009.2@1163.35,-1168.24 ; ED26.2@1180.35,-474.86 1180.35,-426.48 ED27.2@1179.73,-425.86 1178.35,-424.48 ED25.2@1178.35,-325.86 1178.35,-284.65 1201,-262 v2(1214,-262) 1259.06,-262 C91.1@1261,-260.06 1318.94,-260.06 1349.56,-229.44 C92.1@1349.56,-210.86 1365.73,-194.69 R23.2@1365.73,-107.86 ; C48.2@1195.73,-1091.86 1197.18,-1091.86 C4717.2@1197.18,-1134.86 ; C4717.2@1196.73,-1134.86 C4717.2@1197.18,-1134.86 ; C4505.2@1209.61,311.58 1232.73,334.69 v1(1232.73,340.14) U4502.2@1232.73,377.14 ; v2(1226.73,-1159.86) 1201.73,-1134.86 C4717.2@1197.18,-1134.86 ; OLED1.36@1256.16,-899.88 1268.7,-899.88 v2@1311.71,-856.88 ; OU1.2@1280.73,3.35 1280.73,-20.86 v1(1305.73,-45.86) ; v2@1297.73,-961.86 1300.65,-958.94 OLED1.31@1385.29,-958.94 ; v1(1351.57,-735.43) 1378,-761.86 1378,-831.39 OLED1.40@1370.53,-838.86 ; v2(1357.73,-1313.27) OLED1.1@1385.29,-1313.27 1385.29,-1324.09 OLED1.41@1370.53,-1338.86 ; OLED1.7@1385.29,-1242.4 1366.73,-1242.4 1356.03,-1231.7 1356.03,-1195.16 ; OLED1.11@1385.29,-1195.16 1356.03,-1195.16 ; OLED1.15@1385.29,-1147.91 1360.67,-1147.91 1334.73,-1173.86 1356.03,-1195.16 ; OLED1.19@1385.29,-1100.67 1352.54,-1100.67 1338.94,-1087.07 1338.94,-1053.42 ; OLED1.23@1385.29,-1053.42 1338.94,-1053.42 ; OLED1.27@1385.29,-1006.18 1355.4,-1006.18 1338.94,-1022.65 1338.94,-1053.42 ; DC13.1@-62.08,-325.81 v1@-41.99,-345.9 ; v1@-41.99,-345.9 v1@-38.39,-345.9
  BOTTOM w11.81: v1(-1004,-626) -980.02,-649.98 J8.10@-910.92,-649.98 -853.15,-649.98 -832.27,-670.86 C242.2@-832.27,-710.79 ; v2(-787.1,-1332.03) -787.1,-1360.31 ED1.2@-786.56,-1360.86 ; C317.1@-768.44,-903.86 -767.44,-904.86 C316.1@-767.44,-938.86 ; C312.1@-767.44,-1089.86 C313.1@-767.44,-1052.11 ; C314.1@-767.44,-1014.36 C313.1@-767.44,-1052.11 ; v2(-739.27,-938.86) C316.1@-767.44,-938.86 ; v2(-736.27,-1051.11) -768.44,-1051.11 C313.1@-767.44,-1052.11 ; C332.2@-730.2,-1283.08 -729.63,-1283.65 v2(-676.27,-1283.65) ; C239.2@-724.39,-710.79 -724.39,-672.98 -708.27,-656.86 v2(-688.27,-656.86) ; R187.1@-683.27,-1002.48 -766.96,-1002.48 -767.44,-1002 C315.1@-767.44,-976.61 C316.1@-767.44,-938.86 ; v2(-606.5,-1313.08) R5119.2@-574.58,-1313.08 ; ED2.2@-511.99,-1361.86 v2(-485.27,-1361.86) ; C327.1@-468.37,-1279.08 v2(-444.05,-1279.08) ; C290.1@-368.89,-1274.09 -366.83,-1272.03 -351.27,-1272.03 ; v2(-314.27,-1154.86) -314.27,-1213.86 -324.04,-1223.63 C289.2@-353.14,-1223.63 -353.14,-1270.16 -351.27,-1272.03 ; C291.1@-291.27,-1272.03 -351.27,-1272.03 ; v7(-100.27,-1304) -83.28,-1287 C185.1@-74.58,-1287 ; C203.1@-13.8,-1253.17 -13.8,-1270.33 12.73,-1296.86 v2(55.73,-1296.86) C180.1@109.73,-1296.86 ; v2(60.73,-1169.86) 86.11,-1144.48 R484.1@92.73,-1144.48 ; Q7.2@329.91,-1048.86 v2(329.91,-1004.04) ; v2(341.18,-1357.41) C4718.1@341.18,-1332.14 ; C89.1@494.73,-904.98 497.85,-901.86 C68.2@600.41,-901.86 ; C90.1@546.41,-902.86 546.41,-923.54 568.73,-945.86 v2(568.73,-961.86) ; v2(594.73,-961.86) 617.71,-961.86 626.05,-953.52 669.8,-953.52 C65.1@670.78,-954.5 ; C188.1@759.41,-900.69 771.45,-900.69 804.41,-933.66 ; v3(866.56,-459.49) C230.1@887.62,-459.49
  other v1: -1291,-1114.86 -1269,-1114.86 -1247,-1114.86 -448,-1099.86 -1293.27,-1088 -1271.27,-1088 -1249.27,-1088 -231,-671 1220,-576.02 -720.42,-458.9 -688.42,-458.9 -657.42,-458.9 -625.42,-457.9 -594.42,-457.9 -379.42,-447.9 -657.74,-352.46 63.98,-345.48 -469.92,-300.66 1311,-260.06 1340,-257 -658.42,-254.23 -1025.27,-244.86 -781.42,-234.9 -472.42,-223.9 -373.43,-138.57 -378.42,-81.9 -594.3,-77.09 1252.73,-47.86 754,48 -596.27,71 1369,80 480.73,84.14 1369,101.14 -129,233.14 866.73,325.14 -224.27,330.98 -201.77,330.98 -179.27,330.98 1214.73,342.14 1023.73,344.14 105.73,372.14 134.73,372.14 161.73,372.14 -486.27,399.14 -643.27,464.14 -804.27,508.14 -568.27,508.14 -642.27,509.14 -361.27,512.14
  other v2: -267.27,-1358.69 -1223.27,-1352.86 -1095.27,-1352.86 -1051.27,-1352.86 -1253.27,-1350.86 925.73,-1330.86 602.73,-1305.24 925.73,-1293.86 -987.27,-1284.86 -1116.27,-1264.86 -1210.27,-1246.79 -987.27,-1234.86 -1076.08,-1226.86 -1076.08,-1197.86 1049,-1143 820.73,-1065.86 844.73,-1065.86 1350.73,-1053.86 842.73,-974.86 891.73,-963.86 1291.73,-960.86 842.73,-952.86 842.73,-926.86 1312.73,-856.88 1032.35,-836.86 411.73,-772.86 437.73,-718.86 411.73,-717.86 416.73,-666.86 1274.73,-606.86 385,-459 743,-312 575,-265.47 597.73,-265.86 743.73,-265.86 1037,-261
  other v3: 613.12,-789.73 661.84,-536.26
GPIO0-LDO: C276.2 U28.T8 | length 96.6
  TOP w12: v3(713.03,-382.72) U28.T8@751.41,-421.1
  BOTTOM w5: C276.2@713.03,-346.77 C276.2@717.56,-342.24
  BOTTOM w15: v3(713.03,-382.72) C276.2@713.03,-346.77
GPIO1-LDO: C81.2 U28.T7 | length 114.6
  TOP w5: v3(738.62,-380) 738.62,-382.72 U28.T7@777,-421.1
  BOTTOM w5: C81.2@764.21,-347.3 C81.2@769.27,-342.24 C81.2@769.27,-349.35
  BOTTOM w12: v3(738.62,-380) C81.2@769.27,-349.35
HBIAS: C190.2 R144.2 U28.C5 | length 3699.1
  TOP w5: U28.C5@828.18,-753.78 v3(840.98,-766.57)
  TOP w10: v1(-1321.27,85.14) C190.2@-1289.27,85.14 -1294.27,90.14 R144.2@-1294.27,134.14
  SIN03 w4: v1@-1321.27,82.27 v1(-1321.27,85.14) -1293.13,57 -1161,57 -1151,67 -965,67 -952,80 -892,80 -709,263 181,263 203,241 759,241 819,181 819,-75 855,-111 994,-111 1071,-188 1071,-280 1107,-316 1107,-505 1094,-518 1094,-611 947,-758 934,-758 924,-748 909,-748 890.43,-766.57 v3(840.98,-766.57)
HPDI_INT: U1.V18
HPOUTFB: C196.1 C198.2 C200.2 D26.1 J4702.3 R149.2 TP53.1 TP54.1 U28.F2 | length 3304.6
  TOP w8: v1(-830.27,484.14) -812.1,465.97 D26.1@-812.1,430.14 -813.65,428.59 R149.2@-813.65,392.54 -812.1,390.99 C200.2@-812.1,354.94 C198.2@-812.1,317.34 -812.1,299 ; C196.1@-812.1,279.74 -812.1,299 ; v1(-704,249.16) -753.84,299 -812.1,299 ; U28.F2@904.95,-677.01 v3(917.75,-689.81)
  SIN03 w8: v1(-704,249.16) 174.84,249.16 195,229 744,229 806,167 806,-79 849,-122 988,-122 1060,-194 1060,-287 1097,-324 1097,-497 1084,-510 1084,-607 1020,-671 936.55,-671 v3(917.75,-689.81)
  BOTTOM w8: J4702.3@-907.76,504.93 -886.98,484.14 v1(-830.27,484.14) ; TP53.1@-813.65,279.74 TP54.1@-813.65,354.94 -813.65,411.76 v1(-813.27,412.14)
HPOUTL: C211.2 FB1.1 TP51.1 U28.G2 | length 3031.9
  TOP w8: FB1.1@-1015.27,63.14 v1(-1015.27,45.14) -1015.27,26.31 C211.2@-1014.94,25.97 ; U28.G2@904.95,-651.42 v3(917.75,-664.22)
  SIN03 w8: v1(-1015.27,45.14) -867.86,45.14 -708,205 727,205 782,150 782,-93 834,-145 923,-145 981,-203 981,-252 1072,-343 1072,-481 1058,-495 1058,-592 994,-656 925.96,-656 v3(917.75,-664.22)
HPOUTR: C209.2 FB2.1 TP52.1 U28.H1 | length 3038.8
  TOP w8: FB2.1@-1088.63,63.49 v1(-1088.63,45.14) -1088.63,26.33 C209.2@-1088.27,25.97 ; U28.H1@930.54,-625.83 v3(943.34,-638.63)
  SIN03 w8: v1(-1088.63,45.14) -1070.49,27 -863,27 -697,193 719.03,193 770,142.03 770,-100 829,-159 915,-159 963,-207 963,-253 1060,-350 1060,-473 1043,-490 1043,-586 990.37,-638.63 v3(943.34,-638.63)
HS-MIC: C194.2 C196.2 C201.2 D28.1 J4702.2 R144.1 TP50.1 | length 1185
  TOP w8: D28.1@-1260.44,210.81 C194.2@-1260.44,172.48 -1260.44,135.69 R144.1@-1258.89,134.14 -1242.88,118.13 v1(-1242.28,118.13) ; C201.2@-779.82,242.14 C196.2@-779.82,279.74
  SIN03 w8: v1(-1242.28,118.13) -1225.41,135 -907,135 v1(-780,262)
  BOTTOM w8: TP50.1@-1242.28,78.14 v1(-1242.28,118.13) -1284.13,118.13 -1301,135 -1301,248 -1283,266 -1283,462 -1233.18,511.82 J4702.2@-1218.78,511.82
ID0: OLED1.2 R504.2 R1008.1 TP43.1 | length 240.3
  BOTTOM w5: TP43.1@1110.73,-1367.36 1110.73,-1326.86 1133.73,-1303.86 1198.73,-1303.86 ; R1008.1@1198.73,-1322.86 R504.2@1198.73,-1284.86 1217.73,-1284.86 1234.33,-1301.46 OLED1.2@1256.16,-1301.46
ID1: OLED1.3 R505.2 R1009.1 TP44.1 | length 419.9
  SIN03 w4: v2(1198.73,-1219.86) 1198.73,-1255.73 1232.65,-1289.65 v2(1338.94,-1289.65)
  BOTTOM w5: R505.2@1198.73,-1208.86 R1009.1@1198.73,-1170.86 ; TP44.1@1225.73,-1367.36 1249.23,-1343.86 1284.73,-1343.86 v2(1338.94,-1289.65) OLED1.3@1385.29,-1289.65
INT1: R487.1 R5132.1 | length 349.3
  SIN04 w4: v2(-100.89,-1360.24) -12.24,-1360.24 15,-1333 137,-1333 v1@171.14,-1298.86
  BOTTOM w5: v2(-100.89,-1360.24) R487.1@-72.27,-1360.24 ; v1@171.14,-1298.86 R5132.1@194.35,-1298.86
  other v1: 171.14,-1300.86
INT2: R486.1 R5133.1 U1.V7 | length 1427.9
  TOP w4: v1(-63.98,-447.83) U1.V7@-51.18,-435.04
  TOP w5: v1(-74.89,-1135.86) -61.04,-1122 -29.75,-1122 R486.1@-7.27,-1144.48
  SIN03 w4: v1(-74.89,-1135.86) -74.89,-997.89 -31,-954 -31,-860 8,-821 8,-646 -64,-574 -64,-492.89 ; -63.98,-492.87 v1(-63.98,-447.83)
  BOTTOM w5: v1(-74.89,-1135.86) -58.04,-1119 -9,-1119 19,-1091 140,-1091 168.15,-1119.15 168.15,-1146.15 195,-1173 229,-1173 246,-1190 276,-1190 281,-1185 281,-1166 293,-1154 311,-1154 342.73,-1185.73 R5133.1@342.73,-1228.48
IR-RX: U1.AA18
IRQ-AUDIO: R162.1 U1.AA19 U28.L1 | length 1084
  TOP w5: U1.AA19@255.9,-511.82 268.69,-524.61 v1(319.89,-524.61) ; U28.L1@930.54,-549.05 v3(943.34,-536.26)
  SIN03 w4: v1(319.89,-524.61) 319.89,-538.89 325,-544 456,-675 456,-774 468,-786 553,-786 620,-719 712,-719 749,-682 749,-570 768,-551 803,-551 809,-545 934.59,-545 v3(943.34,-536.26)
  BOTTOM w5: R162.1@968.02,-536.26 R162.1@971.41,-532.86
  BOTTOM w8: v3(943.34,-536.26) R162.1@968.02,-536.26
LCD-BL-EN: R90.1 R92.2 U1.C18 | length 3586.9
  TOP w5: U1.C18@230.31,-51.19 243,-38.5 243,15 250,22 289,22 332,65 332,131 v1(323,140)
  SIN03 w4: v2(353,-892) 370,-909 1064,-909 1117,-856 1117,-726 1173,-670 1173,-563 1189,-547 1189,-233 1208,-214 1208,-159 1272,-95 1272,5 1289,22 1289,211 1299,221 1299,274 1262,311 1262,335 1221,376 777,376 764,363 719,363 706,350 537,350 515,328 v1(369,328)
  BOTTOM w5: v1(323,140) 323,265 369,311 v1(369,328) ; v2(353,-892) 353,-875 367.14,-860.86 R92.2@399.41,-860.86 399.79,-860.48 R90.1@445.41,-860.48
LCD-CLK: U1.A18
LCD-D2: U1.A20
LCD-D3: U1.B20
LCD-D4: U1.D18
LCD-D5: U1.D19
LCD-D6: U1.B21
LCD-D7: U1.C20
LCD-D10: U1.C21
LCD-D11: U1.D20
LCD-D12: U1.D21
LCD-D13: U1.E19
LCD-D14: U1.E20
LCD-D15: U1.F18
LCD-D18: U1.A15
LCD-D19: U1.B15
LCD-D20: U1.A16
LCD-D21: U1.B16
LCD-D22: U1.B17
LCD-D23: U1.C16
LCD-DE: U1.B18
LCD-HSYNC: U1.A19
LCD-PWM: R86.1 R88.1 U1.C17 | length 3547.4
  TOP w5: U1.C17@204.72,-51.19 217.52,-38.39 217.52,25.52 229,37 288,37 318,67 318,123 v1(301,140)
  SIN03 w4: v1(349,329) 362.93,342.93 363.85,342 506,342 540,376 591,376 606,391 699.24,391 708.24,400 762.14,400 776.14,386 1225,386 1271,340 1271,319 1309,281 1309,217 1298,206 1298,17 1281,0 1281,-100 1240,-141 1240,-313 1226,-327 1226,-548 1204,-570 1204,-684 1171,-717 1171,-843 1033,-981 891,-981 881.67,-990.33 881.67,-1019.33 860,-1041 782,-1041 720,-1103 720,-1206.72 v2(783.14,-1269.86)
  BOTTOM w5: v1(301,140) 301,260 349,308 v1(349,329) ; R88.1@766.81,-1269.86 v2(783.14,-1269.86)
  BOTTOM w10: R86.1@726.01,-1269.86 R88.1@766.81,-1269.86
LCD-RST: OLED1.4 R75.1 | length 70.3
  BOTTOM w5: R75.1@1198.73,-1246.86 1229.7,-1277.83 OLED1.4@1256.16,-1277.83
LCD-VSYNC: U1.B19
LCD_+V50AP: C48.1 C261.1 C4717.1 D6.2 OLED1.28 R10.1 | length 397.9
  TOP w15: D6.2@1156.74,-1100.87 1156.74,-1090.26 1190,-1057
  SIN03 w15: v2(1034.41,-1294.86) 1034.41,-1232.59 1120.73,-1146.27 v2(1120.73,-1085.86)
  BOTTOM w10: R10.1@1034.41,-1326.6 v2(1034.41,-1294.86) ; C261.1@1199.18,-1010.63 1215.44,-994.37 OLED1.28@1256.16,-994.37
  other v1: 1172,-1045 1193,-1045
  other v2: 1120.73,-1112.86
LCD_-V50AP: C16.2 C236.1 D5.1 OLED1.29 | length 50.3
  TOP w15: D5.1@1329.73,-1076 C236.1@1380,-1076
  other v2: 1323.73,-1004.86 1323.73,-984.86
LCDC_BL: R138.1
LCDIO: C218.1 C222.1 OLED1.30 R504.1 R505.1 U15.5 | length 633
  TOP w5: C218.1@1195.73,-920.63 1225.73,-950.63 v2(1225.73,-970.75)
  SIN03 w15: v2(1120.73,-1268.86) 1120.73,-1234 1120.87,-1233.86 1143.14,-1233.86 1192,-1185 1238,-1185 1256,-1167 1256,-1001.02 v2(1225.73,-970.75)
  BOTTOM w5: v2(1116.31,-1233.86) 1138.35,-1233.86 R505.1@1163.35,-1208.86 ; C222.1@1200.18,-973.63 C222.1@1203.06,-970.75
  BOTTOM w8: v2(1120.73,-1268.86) 1147.35,-1268.86 R504.1@1163.35,-1284.86
  BOTTOM w12: C222.1@1203.06,-970.75 v2(1225.73,-970.75) OLED1.30@1256.16,-970.75
LIGHT_INT: ED34.1 J9.6 U1.Y6 | length 3574.8
  TOP w4: v1(-89.57,-499.02) U1.Y6@-76.77,-486.23
  TOP w5: v1(-116,-1008) -96,-988 26,-988 44,-970 140,-970 170,-940 v1(234,-940) ; v1(636.47,27.14) 655.47,8.14 J9.6@655.47,-40.86
  SIN03 w4: v1(-116,-1008) -42,-934 -42,-851 -2,-811 -2,-652 -74,-580 -74,-514.59 v1(-89.57,-499.02) ; v1(234,-940) 302,-872 360,-872 387.1,-899.1 1059.9,-899.1 1107.1,-851.9 1107.1,-721.9 1165,-664 1165,-558 1181,-542 1181,-249 1172,-240 v1(1172,-213)
  BOTTOM w5: ED34.1@708.93,-35.86 686.93,-13.86 677.47,-13.86 v1(636.47,27.14) 622,41.61 622,52.88 640.12,71 764.88,71 777,58.88 777,-110.97 819.03,-153 1074,-153 1134,-213 v1(1172,-213)
LRADC0: C42.2 U1.W15 | length 85.9
  TOP w4: U1.W15@153.54,-460.63 v1(166.33,-473.43)
  BOTTOM w5: v1(166.33,-473.43) 192.29,-473.43 C42.2@221.86,-503
MBIAS: U28.C6
MCLK-IN: U24.30
MENU: R133.2 R134.1 TP67.1 | length 102.5
  BOTTOM w5: TP67.1@1315.73,-574.86 1331.35,-559.24 R134.1@1331.35,-514.86 R133.2@1331.35,-478.86
MIC1N: U28.B5
MIC1P: U28.A5
MIC2N: C198.1 U28.B4 | length 3532.9
  TOP w8: -750.07,317.34 C198.1@-779.82,317.34 -699.34,317.34 -678.84,296.84 v1(-678.84,286) ; v3(840.98,-792.16) U28.B4@853.77,-779.37
  SIN03 w8: v1(-678.84,286) -677.84,287 -51.2,287 8.8,347 51.2,347 111.2,287 532,287 539,287 565,313 826,313 841,298 1146,298 1160,312 1200.47,312 1243,269.47 1243,131.53 1217,105.53 1217,-95 1189,-123 1129.82,-123 1100,-152.82 1100,-272 1115,-287 1129,-301 1129,-514 1114,-529 1114,-631 1000,-745 975,-745 927.84,-792.16 v3(840.98,-792.16)
MIC2P: C194.1 U28.A4 | length 4249.5
  TOP w8: v1(-1321.61,172.48) C194.1@-1292.72,172.48 ; v3(840.98,-817.75) U28.A4@853.77,-804.96
  SIN03 w8: v1(-1321.61,172.48) -1321.61,137.61 -1266,82 -1184,82 -1154,112 -893,112 -704,301 -57,301 3,361 57,361 117,301 532,301 559,328 835,328 852.86,310.14 1141.14,310.14 1157,326 1203.44,326 1220.44,309 1234.73,294.72 1255,274.44 1255,126.56 1229,100.56 1229,-99.97 1193.97,-135 1139.03,-135 1115,-159.03 1115,-266 1142,-293 1142,-520 1126,-536 1126,-640 1005,-761 982,-761 938,-805 853.73,-805 v3(840.98,-817.75)
MIPI-CSI2-CLKN: U1.T21
MIPI-CSI2-CLKP: U1.T20
MIPI-CSI2-D0N: U1.U19
MIPI-CSI2-D0P: U1.V19
MIPI-CSI2-D1N: U1.T19
MIPI-CSI2-D1P: U1.U20
MIPI-CSI2-D2N: U1.R21
MIPI-CSI2-D2P: U1.R20
MIPI-CSI2-D3N: U1.P20
MIPI-CSI2-D3P: U1.R19
MIPI-DSI-CKN: OLED1.18 U1.G18 | length 1908.5
  TOP w4: v1(217.51,-140.76) U1.G18@230.31,-153.55
  SIN04 w4.5: v1(217.51,-140.76) 252.76,-140.76 262,-150 311,-150 318.08,-157.08 326.08,-157.08 340.5,-171.5 426.93,-171.5 462.43,-207 567.5,-207 605,-244.5 1055.65,-244.5 1130.12,-318.97 1130.12,-854.51 1279,-1003.38 1279,-1061.83 v2(1228.35,-1112.48)
  BOTTOM w4: v2(1228.35,-1112.48) OLED1.18@1256.16,-1112.48
MIPI-DSI-CKP: OLED1.16 U1.G19 | length 1960.1
  TOP w4: v1(243.11,-115.16) 243.11,-140.76 U1.G19@255.9,-153.55
  SIN04 w4.5: v1(243.11,-115.16) 267.44,-139.5 315.35,-139.5 322.42,-146.58 330.42,-146.58 344.85,-161 431.28,-161 466.78,-196.5 571.85,-196.5 609.35,-234 1060,-234 1140.62,-314.62 1140.62,-850.16 1289.5,-999.04 1289.5,-1068.35 1246.42,-1111.42 1246.42,-1118.03 v2(1228.35,-1136.1)
  BOTTOM w4: v2(1228.35,-1136.1) OLED1.16@1256.16,-1136.1
MIPI-DSI-D0N: OLED1.26 U1.H20 | length 1695.9
  TOP w4: v1(268.7,-191.93) U1.H20@281.5,-179.14
  SIN04 w4.5: v1(268.7,-191.93) 290.77,-214 359.87,-214 413.87,-268 450,-268 501.5,-319.5 606.35,-319.5 629.35,-342.5 775.65,-342.5 809.15,-309 981.85,-309 1014.35,-341.5 1048.5,-341.5 1081.5,-374.5 1081.5,-897.65 1155.5,-971.65 1155.5,-995.5 1177.99,-1017.99 v2(1228.35,-1017.99)
  BOTTOM w4: v2(1228.35,-1017.99) OLED1.26@1256.16,-1017.99
MIPI-DSI-D0P: OLED1.24 U1.J19 | length 1695.1
  TOP w4: U1.J19@255.9,-204.73 v1(268.7,-217.52)
  SIN04 w4.5: v1(268.7,-217.52) 275.67,-224.5 355.52,-224.5 409.52,-278.5 445.65,-278.5 497.15,-330 602,-330 625,-353 780,-353 813.5,-319.5 977.5,-319.5 1010,-352 1044.15,-352 1071,-378.85 1071,-902 1145,-976 1145,-999.85 1174.15,-1029 1215.74,-1029 v2(1228.35,-1041.61)
  BOTTOM w4: v2(1228.35,-1041.61) OLED1.24@1256.16,-1041.61
MIPI-DSI-D1N: OLED1.22 U1.G20 | length 1750.5
  TOP w4: U1.G20@281.5,-153.55 294.3,-166.35 v1(294.3,-191.93)
  SIN04 w4.5: v1(294.3,-191.93) 303.37,-201.01 417.16,-201.01 509.65,-293.5 995.5,-293.5 1025,-323 1068,-323 1100.62,-355.62 1100.62,-880.62 1175,-955 1175,-987 1187,-999 1232.88,-999 1247,-1013.12 1247,-1046.59 v2(1228.35,-1065.24)
  BOTTOM w4: v2(1228.35,-1065.24) OLED1.22@1256.16,-1065.24
MIPI-DSI-D1P: OLED1.20 U1.H19 | length 1802.1
  TOP w4: U1.H19@255.9,-179.14 v1(268.7,-166.34)
  SIN04 w4.5: v1(268.7,-166.34) 278.36,-176 309,-176 323.51,-190.51 421.51,-190.51 514,-283 999.85,-283 1029.35,-312.5 1072.35,-312.5 1111.12,-351.27 1111.12,-876.27 1185.5,-950.65 1185.5,-982.65 1191.35,-988.5 1237.23,-988.5 1244.81,-996.08 1257.5,-1008.77 1257.5,-1059.71 v2(1228.35,-1088.86)
  BOTTOM w4: v2(1228.35,-1088.86) OLED1.20@1256.16,-1088.86
MIPI-DSI-D2N: OLED1.14 U1.F21 | length 2012.7
  TOP w4: U1.F21@307.09,-127.96 332.69,-127.96 v1(345.48,-115.17)
  SIN04 w4.5: v1(345.48,-115.17) 353.03,-122.71 375.43,-122.71 383.72,-131 454,-131 488.81,-165.81 1052.81,-165.81 1166.12,-279.12 1166.12,-830.12 1236.26,-900.26 1254,-918 1290,-918 1325.5,-953.5 1335.35,-953.5 1350.5,-968.65 1350.5,-1023.35 1320,-1053.85 1320,-1089.85 1263.5,-1146.35 1263.5,-1158.5 1272,-1167 1279.59,-1167 v3(1286.86,-1159.72)
  BOTTOM w4: OLED1.14@1256.16,-1159.72 v3(1286.86,-1159.72) v3@1287.73,-1160.59
MIPI-DSI-D2P: OLED1.12 U1.G21 | length 2012.6
  TOP w4: U1.G21@307.09,-153.55 319.89,-140.76 v1(345.48,-140.76)
  SIN04 w4.5: v1(345.48,-140.76) 353.03,-133.21 371.08,-133.21 379.37,-141.5 449.65,-141.5 484.46,-176.31 1048.46,-176.31 1155.62,-283.47 1155.62,-834.47 1249.65,-928.5 1285.65,-928.5 1321.15,-964 1331,-964 1340,-973 1340,-1019 1309.5,-1049.5 1309.5,-1085.5 1253,-1142 1253,-1162.85 1267.15,-1177 1283.14,-1177 v3(1287.73,-1181.59)
  BOTTOM w4: OLED1.12@1256.16,-1183.35 1257.92,-1181.59 v3(1287.73,-1181.59)
MIPI-DSI-D3N: OLED1.10 U1.F19 | length 2198.8
  TOP w4: U1.F19@255.9,-127.96 v1(268.7,-115.17)
  SIN04 w4.5: v1(268.7,-115.17) 282.53,-129 303,-129 333,-99 376,-99 385.5,-108.5 457.65,-108.5 495.65,-146.5 1070.67,-146.5 1183.55,-259.38 1183.55,-820.4 1258.65,-895.5 1312.5,-895.5 1342.5,-925.5 ; v2(1228.35,-1206.97) 1233.38,-1212 1286,-1212 1367,-1131 1367,-949.85 1342.58,-925.42
  BOTTOM w4: v2(1228.35,-1206.97) OLED1.10@1256.16,-1206.97
MIPI-DSI-D3P: OLED1.8 U1.F20 | length 2209.2
  TOP w4: U1.F20@281.5,-127.96 v1(294.3,-115.17)
  SIN04 w4.5: v1(294.3,-115.17) 296.83,-115.17 323.5,-88.5 380.35,-88.5 389.85,-98 462,-98 500,-136 1075.02,-136 1194.05,-255.03 1194.05,-816.05 1263,-885 1316.85,-885 1349.92,-918.08 ; v2(1228.35,-1230.59) 1236.44,-1222.5 1254,-1222.5 ; 1247,-1222.5 1254,-1222.5 ; 1350,-918 1377.5,-945.5 1377.5,-1135.35 1290.35,-1222.5 1254,-1222.5
  BOTTOM w4: v2(1228.35,-1230.59) OLED1.8@1256.16,-1230.59
MS-INT: R483.2 R488.2 U1.N21 | length 2175.5
  TOP w5: R488.2@-155.27,-1359.86 v2(-128.27,-1359.86) ; v2(54.35,-1358.24) R483.2@82.73,-1358.24 ; v1@245,-857 293,-857 362,-788 362,-528 349,-515 349,-349 U1.N21@307.09,-307.09
  SIN03 w4: v1(245,-856) 211,-856 191,-876 191,-997 244,-1050 445,-1050 519,-1124 v1(519,-1318)
  SIN04 w4: v2(-128.27,-1359.86) -112.13,-1376 -12,-1376 21,-1343 39.11,-1343 v2(54.35,-1358.24) 139.76,-1358.24 157,-1341 244,-1341 257,-1354 305,-1354 339,-1320 468,-1320 484,-1304 505,-1304 v1(519,-1318)
N03126: DR2.2 DU1.B3 | length 136
  TOP w4: -722.42,-32.86 -722.42,-64.98 -711.42,-75.98 -699.62,-75.98 -690.08,-85.53 -677.35,-85.53 DU1.B3@-674.99,-87.89
  TOP w5: -722.42,-32.86 -722.42,-24.86 -715.27,-17.71 DR2.2@-715.27,11.14
N03128: DR4.2 DU1.B4 | length 143.4
  TOP w4: -693.77,-38.86 -693.77,-66.83 -684.72,-75.89 -655.49,-75.89 DU1.B4@-643.49,-87.89
  TOP w5: -693.77,-38.86 -693.77,-29.77 -678.27,-14.27 DR4.2@-678.27,11.14
N17860835: C235.2 U24.2 | length 109.7
  TOP w15: U24.2@-1040.65,-1128.05 -1040.65,-1185.8 ccw(c-974.49,-1185.8) C235.2@-1021.27,-1232.57
N17860908: R196.2 U24.24 | length 155.3
  TOP w10: v2(-828.27,-761.86) -796.27,-729.86 -775.27,-729.86 -757.18,-711.77 U24.24@-757.18,-673.33
  BOTTOM w5: R196.2@-853.27,-761.86 v2(-828.27,-761.86)
N17860913: L10.2 U24.21
  other v2: -717.27,-778.86 -716.27,-756.86
N17860915: R192.1 R466.2 U24.29 | length 144
  TOP w5: v2(-934.35,-712.78) U24.29@-934.35,-673.33
  BOTTOM w5: R466.2@-993.27,-771.86 R192.1@-957.27,-771.86 -957.27,-735.7 v2(-934.35,-712.78)
N17860923: R195.2 U24.17 | length 310.7
  TOP w5: v2(-919.27,-978.86) -897.02,-956.61 -818.61,-956.61 -762.69,-900.69 U24.17@-671.55,-900.69
  BOTTOM w5: v2(-919.27,-978.86) R195.2@-888.65,-978.86
N17860980: C241.1 R183.2 R185.2 Y1.3 | length 126
  BOTTOM w5: R185.2@-583.27,-1125.86 R183.2@-544,-1125.86 ; C241.1@-564.82,-1161.86 -544,-1141.04 R183.2@-544,-1125.86 ; R183.2@-544,-1124.69 R183.2@-544,-1125.86 ; Y1.3@-505.99,-1132.83 -512.96,-1125.86 R183.2@-544,-1125.86
N17861369: R183.1 R184.1 R186.1 | length 79.7
  BOTTOM w5: R186.1@-583,-1048.69 -583.27,-1048.96 R184.1@-583.27,-1088.86 -582.82,-1089.31 R183.1@-544,-1089.31
N17861416: C242.1 L10.1 U24.23
  other v2: -764.27,-759.86 -788.27,-758.86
